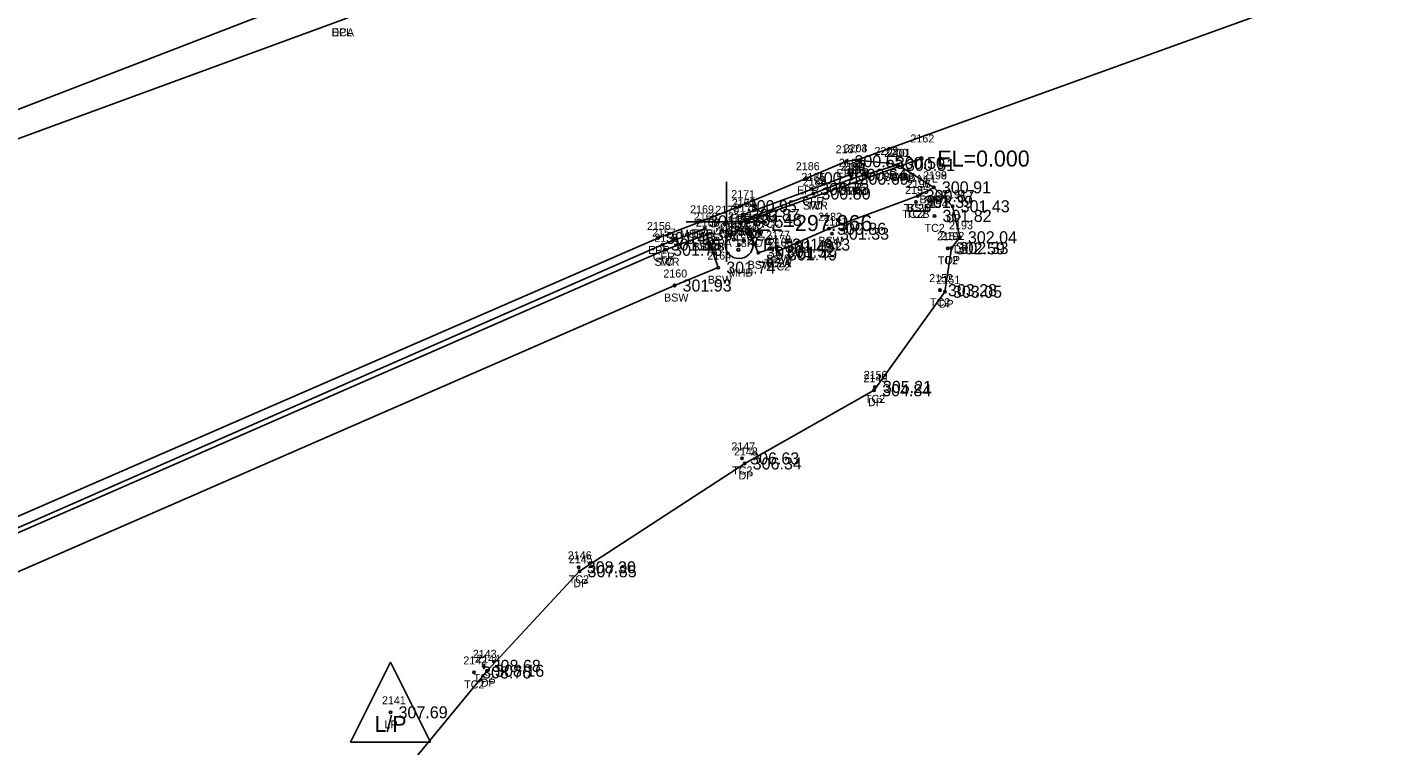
# Model space of a CAD drawing. Extents: x 1970076 to 1971136, y 803126 to 804215.
# Drawn here: x 1970746.3 to 1970917.1, y 803587.1 to 803676.7 of the extents above; entities that cross this region are included whole.
import ezdxf

# ---------------------------------------------------------------- set-up
doc = ezdxf.new("R2010")
doc.units = 0
for name, color, linetype in [('RD_EX_Conc', 7, 'Continuous'), ('RD_EX_Conc_txCode', 7, 'Continuous'), ('RD_EX_DR_Inlet', 7, 'Continuous'), ('RD_EX_DR_Inlet_txCode', 7, 'Continuous'), ('RD_EX_DR_Pipe', 7, 'Continuous'), ('RD_EX_DR_Pipe_txCode', 7, 'Continuous'), ('RD_EX_Driveway', 7, 'Continuous'), ('RD_EX_Driveway_txCode', 7, 'Continuous'), ('RD_EX_Misc', 7, 'Continuous'), ('RD_EX_Misc_txCode', 7, 'Continuous'), ('RD_EX_Road', 7, 'Continuous'), ('RD_EX_Road_txCode', 7, 'Continuous'), ('RD_EX_TX_Conc_ELEV', 7, 'Continuous'), ('RD_EX_TX_DR_Inlet_ELEV', 7, 'Continuous'), ('RD_EX_TX_Driveway_ELEV', 7, 'Continuous'), ('RD_EX_TX_Misc_ELEV', 7, 'Continuous'), ('RD_EX_TX_Road_ELEV', 7, 'Continuous'), ('RD_EX_TX_UT_ELEV', 7, 'Continuous'), ('RD_EX_UT', 7, 'Continuous'), ('RD_EX_UT_txCode', 7, 'Continuous'), ('RD_SMD_Locator', 7, 'Continuous'), ('RD_TX_Pipe_ElevEX', 7, 'Continuous')]:
    doc.layers.add(name, color=color, linetype=linetype)

msp = doc.modelspace()

# ---------------------------------------------------------------- linework, layer by layer
at = {"layer": 'RD_EX_Conc'}
for points in [[(1970835.66, 803653.31), (1970844.35, 803656.53), (1970849.04, 803658.31), (1970849.28, 803657.82)], [(1970835.92, 803652.69), (1970844.52, 803655.97), (1970849.28, 803657.82), (1970855.07, 803659.55)], [(1970835.92, 803652.69), (1970837.62, 803648.58), (1970839.96, 803649.32), (1970840.09, 803648.76), (1970846.46, 803651.57), (1970857.54, 803655.67), (1970859.56, 803656.74)], [(1970686.21, 803560.33), (1970689.09, 803570.66), (1970697.16, 803583.69), (1970713.44, 803597.13), (1970734.87, 803609.74), (1970825.69, 803649.6), (1970830.95, 803651.58)], [(1970686.87, 803560.28), (1970689.49, 803570.5), (1970697.58, 803583.18), (1970713.81, 803596.63), (1970735.37, 803609.4), (1970825.99, 803648.95), (1970831.2, 803650.84)], [(1970691.16, 803559.72), (1970693.96, 803569.01), (1970700.53, 803580.02), (1970716.15, 803592.81), (1970737.19, 803605.29), (1970827.17, 803644.49), (1970832.63, 803646.72), (1970831.2, 803650.84)]]:
    msp.add_lwpolyline(points, dxfattribs=at)
at = {"layer": 'RD_EX_DR_Inlet'}
for centre, radius in [((1970835.23, 803649.6), 1.75), ((1970834.57, 803650.23), 0.175), ((1970835.79, 803650.16), 0.175), ((1970835.14, 803648.94), 0.175)]:
    msp.add_circle(centre, radius, dxfattribs=at)
at = {"layer": 'RD_EX_DR_Pipe'}
for p, q in [((1970722.35, 803657.7), (1970845.03, 803704.96)), ((1970835.38, 803652.29), (1970858, 803660.34))]:
    msp.add_line(p, q, dxfattribs=at)
at = {"layer": 'RD_EX_Driveway'}
msp.add_lwpolyline([(1970781.41, 803517.89), (1970780.19, 803566.79), (1970783.09, 803572.02), (1970790.56, 803580.4), (1970803.75, 803596.41), (1970815.3, 803608.83), (1970835.93, 803622.28), (1970852.1, 803631.42), (1970860.94, 803643.71), (1970861.75, 803649.17), (1970862.81, 803650.51), (1970861.9, 803654.38), (1970859.56, 803656.74), (1970855.07, 803659.55), (1970853.81, 803659.78), (1970849.95, 803660.12)], dxfattribs=at)
at = {"layer": 'RD_EX_Misc'}
for p, q in [((1970833.64, 803647.45), (1970833.64, 803657.45)), ((1970828.64, 803652.45), (1970838.64, 803652.45))]:
    msp.add_line(p, q, dxfattribs=at)
at = {"layer": 'RD_EX_Road'}
for points in [[(1970591.95, 803626.63), (1970595.64, 803624.22), (1970603.94, 803620.23), (1970610.89, 803618.12), (1970618.56, 803616.95), (1970618.56, 803616.95), (1970625.29, 803616.42), (1970639.01, 803619.1), (1970654.35, 803624.92), (1970666.82, 803630.04), (1970700.04, 803645.21), (1970717.46, 803652.2), (1970737.46, 803660.02), (1970785.58, 803677.59), (1970806.16, 803685.61), (1970810.51, 803687.07), (1970832.41, 803695.41), (1970845.91, 803700.39), (1970902.88, 803721.47)], [(1970707.08, 803502.25), (1970704.83, 803505.7), (1970695.33, 803521.24), (1970688.51, 803536.11), (1970684.99, 803546.09), (1970684.43, 803549.97), (1970685, 803560.52), (1970685, 803560.52), (1970687.77, 803571.3), (1970696.05, 803584.62), (1970712.98, 803598.27), (1970734.15, 803610.93), (1970825.09, 803650.42), (1970830.48, 803652.5), (1970835.31, 803654.39), (1970843.69, 803657.88), (1970848.64, 803660), (1970849.95, 803660.12), (1970917.12, 803684.38)]]:
    msp.add_lwpolyline(points, dxfattribs=at)
at = {"layer": 'RD_EX_UT'}
for p, q in [((1970786.69, 803587.49), (1970791.69, 803597.49)), ((1970791.69, 803597.49), (1970796.69, 803587.49)), ((1970786.69, 803587.49), (1970796.69, 803587.49))]:
    msp.add_line(p, q, dxfattribs=at)
at = {"layer": 'RD_SMD_Locator'}
for centre, radius in [((1970848.64, 803660), 0.15), ((1970849.95, 803660.12), 0.15), ((1970849.95, 803660.12), 0.15), ((1970853.81, 803659.78), 0.15), ((1970855.07, 803659.55), 0.15), ((1970855.07, 803659.55), 0.15), ((1970858, 803660.34), 0.2), ((1970843.69, 803657.88), 0.15), ((1970849.04, 803658.31), 0.15), ((1970844.35, 803656.53), 0.15), ((1970849.28, 803657.82), 0.15), ((1970849.28, 803657.82), 0.15), ((1970849.28, 803657.82), 0.15), ((1970859.56, 803656.74), 0.15), ((1970859.56, 803656.74), 0.15), ((1970844.52, 803655.97), 0.15), ((1970844.52, 803655.97), 0.15), ((1970857.32, 803654.93), 0.15), ((1970857.32, 803654.93), 0.15), ((1970857.54, 803655.67), 0.15), ((1970857.54, 803655.67), 0.15), ((1970835.31, 803654.39), 0.15), ((1970835.66, 803653.31), 0.15), ((1970859.64, 803653.18), 0.15), ((1970861.9, 803654.38), 0.15), ((1970830.48, 803652.5), 0.15), ((1970830.95, 803651.58), 0.15), ((1970833.64, 803652.45), 0.15), ((1970835.38, 803652.29), 0.2), ((1970835.92, 803652.69), 0.15), ((1970835.92, 803652.69), 0.15), ((1970835.92, 803652.69), 0.15), ((1970846.46, 803651.57), 0.15), ((1970825.09, 803650.42), 0.15), ((1970825.69, 803649.6), 0.15), ((1970831.2, 803650.84), 0.15), ((1970831.2, 803650.84), 0.15), ((1970831.2, 803650.84), 0.15), ((1970835.23, 803649.6), 0.15), ((1970839.96, 803649.32), 0.15), ((1970846.83, 803650.96), 0.15), ((1970862.81, 803650.51), 0.15), ((1970825.99, 803648.95), 0.15), ((1970825.99, 803648.95), 0.15), ((1970837.62, 803648.58), 0.15), ((1970840.09, 803648.76), 0.15), ((1970840.09, 803648.76), 0.15), ((1970840.33, 803648.37), 0.15), ((1970861.29, 803649.13), 0.15), ((1970861.75, 803649.17), 0.15), ((1970832.63, 803646.72), 0.15), ((1970827.17, 803644.49), 0.15), ((1970860.32, 803643.91), 0.15), ((1970860.94, 803643.71), 0.15), ((1970852.1, 803631.42), 0.15), ((1970852.19, 803631.84), 0.15), ((1970835.61, 803622.91), 0.15), ((1970835.93, 803622.28), 0.15), ((1970815.2, 803609.32), 0.15), ((1970815.3, 803608.83), 0.15), ((1970803.32, 803597.02), 0.15), ((1970803.75, 803596.41), 0.15), ((1970802.13, 803596.2), 0.15), ((1970791.69, 803591.22), 0.15)]:
    msp.add_circle(centre, radius, dxfattribs=at)

# ---------------------------------------------------------------- texts
at = {"layer": 'RD_EX_Conc_txCode'}
for s, p in [('DCA', (1970784.31, 803675.59)), ('2200', (1970853.36, 803660.55)), ('2188', (1970847.69, 803659.31)), ('2190', (1970847.89, 803658.82)), ('2189', (1970847.93, 803658.82)), ('2191', (1970848.22, 803658.82)), ('2185', (1970843.01, 803657.53)), ('SWRB', (1970853.28, 803657.55)), ('2198', (1970858.21, 803657.74)), ('2183', (1970843.17, 803656.97)), ('2184', (1970843.17, 803656.97)), ('CFRB', (1970847.58, 803655.82)), ('CFR', (1970847.81, 803656.31)), ('SWR', (1970847.96, 803655.82)), ('TCB', (1970848.01, 803655.82)), ('2155', (1970855.97, 803655.93)), ('2195', (1970855.97, 803655.93)), ('2196', (1970856.17, 803656.67)), ('2197', (1970856.19, 803656.67)), ('2172', (1970834.32, 803654.31)), ('2173', (1970834.57, 803653.69)), ('2174', (1970834.57, 803653.69)), ('2175', (1970834.57, 803653.69)), ('CFR', (1970843.12, 803654.53)), ('SWR', (1970843.2, 803653.97)), ('TC', (1970843.72, 803653.97)), ('TC2B', (1970855.82, 803653.67)), ('BSW', (1970856.22, 803653.67)), ('BSWB', (1970857.77, 803654.74)), ('2154', (1970858.3, 803654.18)), ('2168', (1970829.58, 803652.58)), ('2182', (1970845.11, 803652.57)), ('2181', (1970845.76, 803651.96)), ('TC2B', (1970855.6, 803652.93)), ('TC2', (1970856.08, 803652.93)), ('2157', (1970824.35, 803650.6)), ('2166', (1970829.81, 803651.84)), ('2165', (1970829.83, 803651.84)), ('2167', (1970829.83, 803651.84)), ('CFRA 12', (1970832.85, 803651.31)), ('SWRA', (1970834.12, 803650.69)), ('BSWA', (1970834.12, 803650.69)), ('TC', (1970835.13, 803650.69)), ('2177', (1970838.61, 803650.32)), ('TC2', (1970858.4, 803651.18)), ('2158', (1970824.64, 803649.95)), ('2159', (1970824.64, 803649.95)), ('CFRB', (1970829.25, 803649.58)), ('SWRB', (1970829.41, 803648.84)), ('BSWB', (1970829.41, 803648.84)), ('TC', (1970830.41, 803648.84)), ('2176', (1970836.25, 803649.58)), ('2178', (1970838.74, 803649.76)), ('2179', (1970838.74, 803649.76)), ('2180', (1970838.95, 803649.37)), ('BSW', (1970845.14, 803649.57)), ('TC2', (1970845.58, 803648.96)), ('2153', (1970859.95, 803650.13)), ('CFR', (1970824.46, 803647.6)), ('SWR', (1970824.67, 803646.95)), ('TC', (1970825.19, 803646.95)), ('2164', (1970831.26, 803647.72)), ('TC2A', (1970838.35, 803646.76)), ('BSW', (1970838.64, 803647.32)), ('BSW', (1970838.77, 803646.76)), ('TC2', (1970860.05, 803647.13)), ('2160', (1970825.77, 803645.49)), ('BSW', (1970836.31, 803646.58)), ('TC2', (1970839.09, 803646.37)), ('BSW', (1970831.31, 803644.72)), ('2152', (1970858.98, 803644.91)), ('BSW', (1970825.86, 803642.49)), ('TC2', (1970859.08, 803641.91)), ('2150', (1970850.8, 803632.84)), ('TC2', (1970850.95, 803629.84)), ('2147', (1970834.26, 803623.91)), ('TC2', (1970834.37, 803620.91)), ('2146', (1970813.83, 803610.32)), ('TC2', (1970813.95, 803607.32)), ('2142', (1970800.78, 803597.2)), ('2143', (1970801.97, 803598.02)), ('TC2', (1970800.89, 803594.2)), ('TC2', (1970802.08, 803595.02))]:
    msp.add_text(s, height=1, dxfattribs=at).set_placement(p)
at = {"layer": 'RD_EX_DR_Inlet_txCode'}
for s, p in [('2163', (1970833.86, 803652.6)), ('MHD', (1970833.94, 803645.6))]:
    msp.add_text(s, height=1, dxfattribs=at).set_placement(p)
at = {"layer": 'RD_EX_DR_Pipe_txCode'}
for s, p in [('2162', (1970856.63, 803662.34)), ('PB NFL', (1970855.37, 803657.34)), ('2161', (1970834.3, 803654.29)), ('PA 18RC', (1970832.54, 803649.29))]:
    msp.add_text(s, height=1, dxfattribs=at).set_placement(p)
at = {"layer": 'RD_EX_Driveway_txCode'}
for s, p in [('2203', (1970848.28, 803661.12)), ('2202', (1970852.14, 803660.78)), ('2201', (1970853.68, 803660.55)), ('DPB', (1970848.69, 803658.12)), ('DP', (1970853.03, 803657.78)), ('DP', (1970854.29, 803657.55)), ('2199', (1970858.21, 803657.74)), ('2194', (1970860.56, 803655.38)), ('DP', (1970858.78, 803654.74)), ('DP', (1970861.12, 803652.38)), ('2192', (1970860.4, 803650.17)), ('2193', (1970861.46, 803651.51)), ('DP', (1970862.03, 803648.51)), ('DP', (1970860.97, 803647.17)), ('2151', (1970859.87, 803644.71)), ('DP', (1970860.16, 803641.71)), ('2149', (1970850.76, 803632.42)), ('DP', (1970851.33, 803629.42)), ('2148', (1970834.59, 803623.28)), ('DP', (1970835.15, 803620.28)), ('2145', (1970813.96, 803609.83)), ('DP', (1970814.52, 803606.83)), ('2144', (1970802.4, 803597.41)), ('DP', (1970802.97, 803594.41))]:
    msp.add_text(s, height=1, dxfattribs=at).set_placement(p)
at = {"layer": 'RD_EX_Misc_txCode'}
for s, p in [('2170', (1970832.26, 803653.45)), ('MSP FLOW LINE', (1970827.84, 803650.45))]:
    msp.add_text(s, height=1, dxfattribs=at).set_placement(p)
at = {"layer": 'RD_EX_Road_txCode'}
for s, p in [('EPL', (1970784.37, 803675.59)), ('2187', (1970847.29, 803661)), ('2204', (1970848.28, 803661.12)), ('2186', (1970842.32, 803658.88)), ('EPR', (1970847.41, 803658)), ('EPR', (1970848.72, 803658.12)), ('2171', (1970834.25, 803655.39)), ('EPR', (1970842.47, 803655.88)), ('2169', (1970829.11, 803653.5)), ('EPR', (1970834.08, 803652.39)), ('2156', (1970823.72, 803651.42)), ('EPR', (1970829.26, 803650.5)), ('EPR', (1970823.86, 803648.42))]:
    msp.add_text(s, height=1, dxfattribs=at).set_placement(p)
at = {"layer": 'RD_EX_TX_Conc_ELEV'}
for s, p in [('300.51', (1970856.07, 803658.8)), ('300.64', (1970850.04, 803657.56)), ('300.69', (1970850.28, 803657.07)), ('300.69', (1970850.28, 803657.07)), ('300.69', (1970850.28, 803657.07)), ('300.73', (1970845.35, 803655.78)), ('300.80', (1970845.52, 803655.22)), ('300.80', (1970845.52, 803655.22)), ('300.87', (1970858.54, 803654.92)), ('300.87', (1970858.54, 803654.92)), ('300.91', (1970860.56, 803655.99)), ('301.39', (1970858.32, 803654.18)), ('301.39', (1970858.32, 803654.18)), ('300.87', (1970836.66, 803652.56)), ('301.48', (1970836.92, 803651.94)), ('301.48', (1970836.92, 803651.94)), ('301.48', (1970836.92, 803651.94)), ('301.82', (1970860.64, 803652.43)), ('301.04', (1970831.95, 803650.83)), ('301.62', (1970832.2, 803650.09)), ('301.62', (1970832.2, 803650.09)), ('301.62', (1970832.2, 803650.09)), ('300.86', (1970847.46, 803650.82)), ('301.33', (1970847.83, 803650.21)), ('301.35', (1970826.69, 803648.85)), ('301.78', (1970826.99, 803648.2)), ('301.78', (1970826.99, 803648.2)), ('301.49', (1970840.96, 803648.57)), ('301.52', (1970841.09, 803648.01)), ('301.52', (1970841.09, 803648.01)), ('302.59', (1970862.29, 803648.38)), ('301.61', (1970838.62, 803647.83)), ('301.49', (1970841.33, 803647.62)), ('301.74', (1970833.63, 803645.97)), ('301.93', (1970828.17, 803643.74)), ('303.28', (1970861.32, 803643.16)), ('305.21', (1970853.19, 803631.09)), ('306.63', (1970836.61, 803622.16)), ('308.30', (1970816.2, 803608.57)), ('308.76', (1970803.13, 803595.45)), ('308.68', (1970804.32, 803596.27))]:
    msp.add_text(s, height=1.5, dxfattribs=at).set_placement(p)
at = {"layer": 'RD_EX_TX_DR_Inlet_ELEV'}
msp.add_text('EL=301.613', height=1.5, dxfattribs=at).set_placement((1970838.23, 803648.85))
at = {"layer": 'RD_EX_TX_Driveway_ELEV'}
for s, p in [('300.50', (1970850.95, 803659.37)), ('300.50', (1970854.81, 803659.03)), ('300.51', (1970856.07, 803658.8)), ('300.91', (1970860.56, 803655.99)), ('301.43', (1970862.9, 803653.63)), ('302.04', (1970863.81, 803649.76)), ('302.33', (1970862.75, 803648.42)), ('303.05', (1970861.94, 803642.96)), ('304.84', (1970853.1, 803630.67)), ('306.34', (1970836.93, 803621.53)), ('307.85', (1970816.3, 803608.08)), ('308.16', (1970804.75, 803595.66))]:
    msp.add_text(s, height=1.5, dxfattribs=at).set_placement(p)
at = {"layer": 'RD_EX_TX_Misc_ELEV'}
msp.add_text('300.85', height=1.5, dxfattribs=at).set_placement((1970834.64, 803651.7))
at = {"layer": 'RD_EX_TX_Road_ELEV'}
for s, p in [('300.55', (1970849.64, 803659.25)), ('300.50', (1970850.95, 803659.37)), ('300.70', (1970844.69, 803657.13)), ('300.95', (1970836.31, 803653.64)), ('301.19', (1970831.48, 803651.75)), ('301.43', (1970826.09, 803649.67))]:
    msp.add_text(s, height=1.5, dxfattribs=at).set_placement(p)
at = {"layer": 'RD_EX_TX_UT_ELEV'}
msp.add_text('307.69', height=1.5, dxfattribs=at).set_placement((1970792.69, 803590.47))
at = {"layer": 'RD_EX_UT'}
msp.add_text('L/P', height=2, dxfattribs=at).set_placement((1970789.68, 803588.78))
at = {"layer": 'RD_EX_UT_txCode'}
for s, p in [('2141', (1970790.62, 803592.22)), ('LP', (1970790.93, 803589.22))]:
    msp.add_text(s, height=1, dxfattribs=at).set_placement(p)
at = {"layer": 'RD_TX_Pipe_ElevEX'}
for s, p in [('EL=0.000', (1970860, 803659.34)), ('EL=297.966', (1970837.38, 803651.29))]:
    msp.add_text(s, height=2, dxfattribs=at).set_placement(p)

doc.saveas('drawing.dxf')
